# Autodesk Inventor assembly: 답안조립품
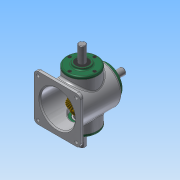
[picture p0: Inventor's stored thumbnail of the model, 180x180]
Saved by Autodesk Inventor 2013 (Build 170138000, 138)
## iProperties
Created: 2015-10
Part Number: 답안조립품
Document SubType Name: Assembly
Designer: Administrator
Author: Administrator
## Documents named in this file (14)
- C:\Users\Administrator\Desktop\451008V1024\답안조립품.iam
- C:\Users\Administrator\Desktop\451008V1024\M4.ipt
- C:\Users\Administrator\Desktop\451008V1024\메인 베벨기어.ipt
- C:\Users\Administrator\Desktop\451008V1024\메인 축.ipt
- 메인 축.ipt
- C:\Users\Administrator\Desktop\451008V1024\베어링 6203.ipt
- C:\Users\Administrator\Desktop\451008V1024\본체.ipt
- C:\Users\Administrator\Desktop\451008V1024\서브 베벨기어.ipt
- C:\Users\Administrator\Desktop\451008V1024\서브 축.ipt
- 서브 축.ipt
- C:\Users\Administrator\Desktop\451008V1024\오일실.ipt
- C:\Users\Administrator\Desktop\451008V1024\커버.ipt
- C:\Users\Administrator\Desktop\451008V1024\키 4x4.ipt
- C:\Users\Administrator\Desktop\451008V1024\키 5x5.ipt
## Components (12 placed, 1 different names)
1. M4:2
2. M4:3
3. M4:4
4. M4:5
5. M4:1
6. M4:7
7. M4:8
8. M4:9
9. M4:6
10. M4:10
11. M4:11
12. M4:12
